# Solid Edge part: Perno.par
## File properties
Author: Luca
Template: Normal.par
Last saved by: Luca
Revision: 5
Application: Solid Edge
Accuracy: 0.990
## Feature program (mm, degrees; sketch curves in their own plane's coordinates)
sketch for "unnamed Protrusion 1" plane through (0, 0, 0) normal (0, 0, 1) x-axis (1, 0, 0)
  circle centre (0, 0) radius 15
extrude "unnamed Protrusion 1" add finite 90 along +normal
chamfer "Smusso_1" setback 1
sketch for "unnamed Cutout 1" plane through (0, 0, 0) normal (0, 0, -1) x-axis (1, 0, 0)
extrude "unnamed Cutout 1" cut through along -normal
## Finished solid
Body 1: solid body, 6 faces, 6 edges, 0 vertices.
  Faces by surface: cone 2, cylinder 2, plane 2
  Edges by curve: circle 6
Bounding box of the edges (mm): 30.000 x 30.000 x 90.000, from (-15, -15, 0) to (15, 15, 90).
Cylindrical faces by radius (mm): R10 x1, R15 x1
Conical faces (half-angle, radius in mm at the cone's reference point): 45 deg R14 x1, 45 deg R15 x1
Planar faces by outward normal: +z 1, -z 1
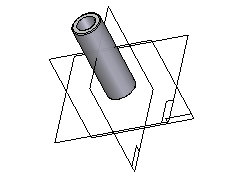
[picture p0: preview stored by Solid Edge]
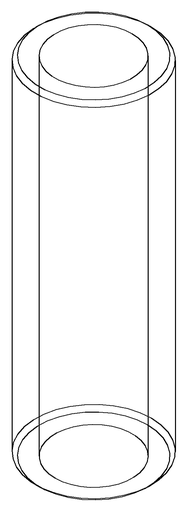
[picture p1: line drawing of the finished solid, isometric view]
